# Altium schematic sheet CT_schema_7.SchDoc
size 252 x 159 mm
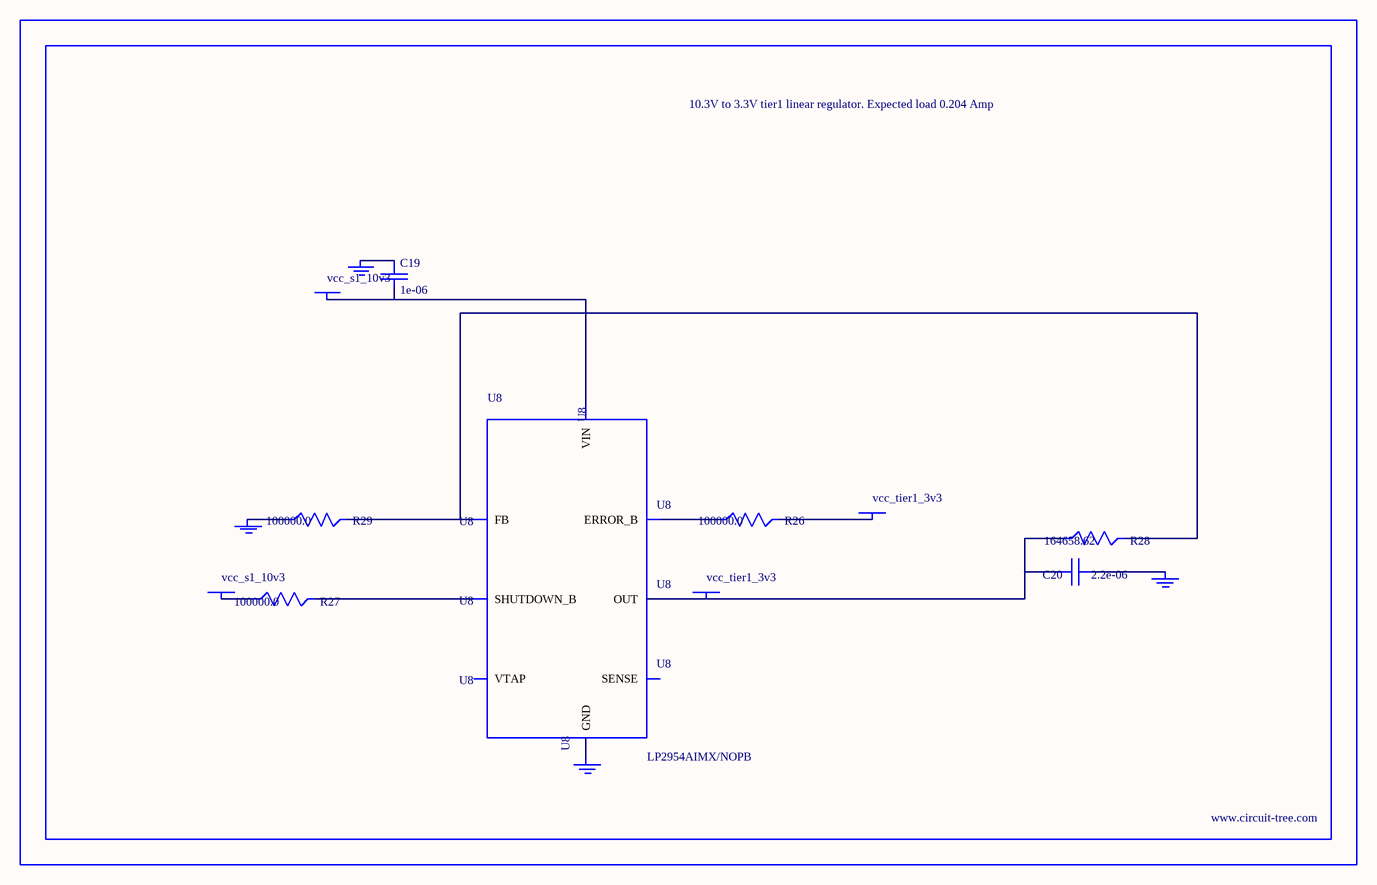
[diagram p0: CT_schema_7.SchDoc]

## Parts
BORDER6  (no value)
C19  1e-06  [EXV-9B]
C20  2.2e-06  [EXV-9B]
GND_INSTANCE_6_0  (no value)
GND_INSTANCE_6_1  (no value)
GND_INSTANCE_6_2  (no value)
GND_INSTANCE_6_3  (no value)
POWER_INSTANCE_6_0  vcc_s1_10v3
POWER_INSTANCE_6_1  vcc_tier1_3v3
POWER_INSTANCE_6_2  vcc_s1_10v3
POWER_INSTANCE_6_3  vcc_tier1_3v3
R26  100000.0  [R0603]
R27  100000.0  [R0603]
R28  164658.62  [R0603]
R29  100000.0  [R0603]
U8  LP2954AIMX/NOPB  [LP2954]

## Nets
NetC19_1: C19.1 GND_INSTANCE_6_2.0(GND)
NetC19_2: C19.2 POWER_INSTANCE_6_2.0(PWR) U8.8(VIN)
NetC20_1: C20.1 GND_INSTANCE_6_0.0(GND)
NetC20_2: C20.2 POWER_INSTANCE_6_3.0(PWR) R28.1 U8.1(OUT)
NetGND_INSTANCE_6_1_0: GND_INSTANCE_6_1.0(GND) R29.1
NetGND_INSTANCE_6_3_0: GND_INSTANCE_6_3.0(GND) U8.4(GND)
NetPOWER_INSTANCE_6_0_0: POWER_INSTANCE_6_0.0(PWR) R27.1
NetPOWER_INSTANCE_6_1_0: POWER_INSTANCE_6_1.0(PWR) R26.2
NetR26_1: R26.1 U8.5(ERROR_B)
NetR27_2: R27.2 U8.3(SHUTDOWN_B)
NetR28_2: R28.2 R29.2 U8.7(FB)

Not connected (* = marked no-connect by the designer): U8 2(SENSE) 6(VTAP)

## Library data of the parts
BORDER6 = BORDER_PAGE6
C19 = EDK105M050A9BAA
C20 = EDK225M050A9BAA
GND_INSTANCE_6_0-GND_INSTANCE_6_3 = GND
POWER_INSTANCE_6_0-POWER_INSTANCE_6_3 = PWR
R26 R27 R29 = RC0603JR-07100KL
R28 = R28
